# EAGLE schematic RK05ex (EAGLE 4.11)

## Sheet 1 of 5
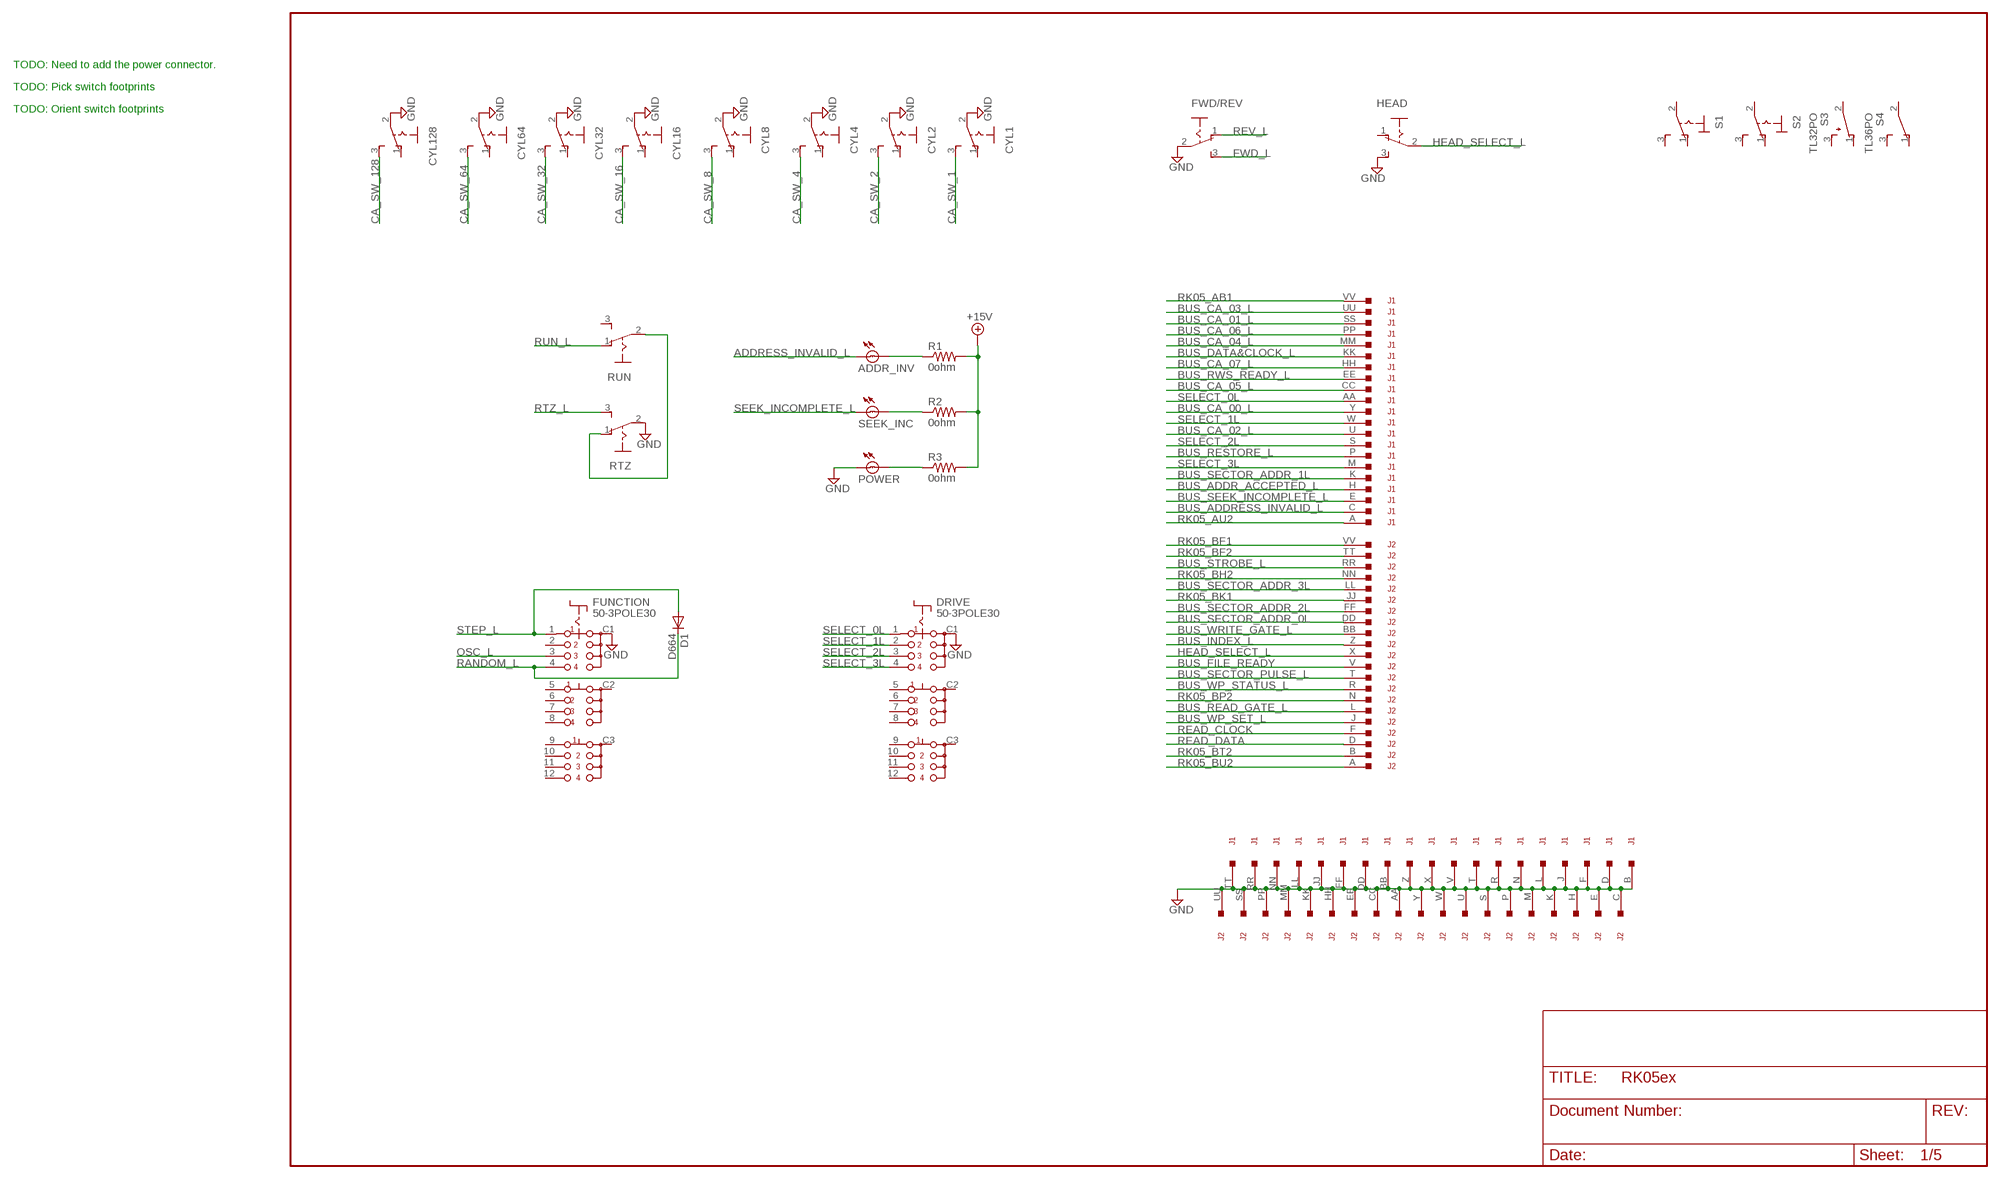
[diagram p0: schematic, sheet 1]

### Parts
ADDR_INV  BULB  [BULB]
CYL1  255SB  [255SB]
CYL2  255SB  [255SB]
CYL4  255SB  [255SB]
CYL8  255SB  [255SB]
CYL16  255SB  [255SB]
CYL32  255SB  [255SB]
CYL64  255SB  [255SB]
CYL128  255SB  [255SB]
D1  D664  1N4148  [DO35-10]
DRIVE  50-3POLE30  [50-3POLE30]
FUNCTION  50-3POLE30  [50-3POLE30]
FWD/REV  255SB  [255SB]
HEAD  255SB  [255SB]
J1  DEC40PINSV  [DEC40PINV]
J2  DEC40PINSV  [DEC40PINV]
POWER  BULB  [BULB]
R1  0ohm  R-US_0207/10  [0207/10]
R2  0ohm  R-US_0207/10  [0207/10]
R3  0ohm  R-US_0207/10  [0207/10]
RTZ  255SB  [255SB]
RUN  255SB  [255SB]
S1  320-916  [320-916]
S2  M9040P  [M9040P]
S3  TL32PO  [TL3XPO]
S4  TL36PO  [TL3XPO]
SEEK_INC  BULB  [BULB]

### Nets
+15V: R1.2 R2.2 R3.2 ; also sheet 3
ADDRESS_INVALID_L: ADDR_INV.B ; also sheet 3
BUS_ADDR_ACCEPTED_L: J1.H ; also sheet 5
BUS_ADDRESS_INVALID_L: J1.C ; also sheet 3,5
BUS_CA_00_L: J1.Y ; also sheet 4,5
BUS_CA_01_L: J1.SS ; also sheet 4,5
BUS_CA_02_L: J1.U ; also sheet 4,5
BUS_CA_03_L: J1.UU ; also sheet 4,5
BUS_CA_04_L: J1.MM ; also sheet 4,5
BUS_CA_05_L: J1.CC ; also sheet 4,5
BUS_CA_06_L: J1.PP ; also sheet 4,5
BUS_CA_07_L: J1.HH ; also sheet 4,5
BUS_DATA&CLOCK_L: J1.KK ; also sheet 2,5
BUS_FILE_READY: J2.V ; also sheet 5
BUS_INDEX_L: J2.Z ; also sheet 2,5
BUS_READ_GATE_L: J2.L ; also sheet 5
BUS_RESTORE_L: J1.P ; also sheet 3,5
BUS_RWS_READY_L: J1.EE ; also sheet 3,5
BUS_SECTOR_ADDR_0L: J2.DD ; also sheet 2,5
BUS_SECTOR_ADDR_1L: J1.K ; also sheet 2,5
BUS_SECTOR_ADDR_2L: J2.FF ; also sheet 2,5
BUS_SECTOR_ADDR_3L: J2.LL ; also sheet 2,5
BUS_SECTOR_PULSE_L: J2.T ; also sheet 5
BUS_SEEK_INCOMPLETE_L: J1.E ; also sheet 3,5
BUS_STROBE_L: J2.RR ; also sheet 3,5
BUS_WP_SET_L: J2.J ; also sheet 5
BUS_WP_STATUS_L: J2.R ; also sheet 5
BUS_WRITE_GATE_L: J2.BB ; also sheet 2,5
CA_SW_1: CYL1.3(S) ; also sheet 4
CA_SW_2: CYL2.3(S) ; also sheet 4
CA_SW_4: CYL4.3(S) ; also sheet 4
CA_SW_8: CYL8.3(S) ; also sheet 4
CA_SW_16: CYL16.3(S) ; also sheet 4
CA_SW_32: CYL32.3(S) ; also sheet 4
CA_SW_64: CYL64.3(S) ; also sheet 4
CA_SW_128: CYL128.3(S) ; also sheet 4
FWD_L: FWD/REV.3(S) ; also sheet 3
GND: CYL1.2(P) CYL2.2(P) CYL4.2(P) CYL8.2(P) CYL16.2(P) CYL32.2(P) CYL64.2(P) CYL128.2(P) DRIVE.C1(A) FUNCTION.C1(A) FWD/REV.2(P) HEAD.3(S) J1.B J1.BB J1.D J1.DD J1.F J1.FF J1.J J1.JJ J1.L J1.LL J1.N J1.NN J1.R J1.RR J1.T J1.TT J1.V J1.X J1.Z J2.AA J2.C J2.CC J2.E J2.EE J2.H J2.HH J2.K J2.KK J2.M J2.MM J2.P J2.PP J2.S J2.SS J2.U J2.UU J2.W J2.Y POWER.B RTZ.2(P) ; also sheet 2,3,4,5
HEAD_SELECT_L: HEAD.2(P) J2.X ; also sheet 5
N$30: RTZ.1(O) RUN.2(P)
N$37: ADDR_INV.A R1.1
N$38: R2.1 SEEK_INC.A
N$39: POWER.A R3.1
OSC_L: FUNCTION.3(A3) ; also sheet 3
RANDOM_L: D1.C FUNCTION.4(A4) ; also sheet 3
READ_CLOCK: J2.F ; also sheet 5
READ_DATA: J2.D ; also sheet 5
REV_L: FWD/REV.1(O) ; also sheet 3
RK05_AB1: J1.VV ; also sheet 5
RK05_AU2: J1.A ; also sheet 5
RK05_BF1: J2.VV ; also sheet 5
RK05_BF2: J2.TT ; also sheet 5
RK05_BH2: J2.NN ; also sheet 5
RK05_BK1: J2.JJ ; also sheet 5
RK05_BP2: J2.N ; also sheet 5
RK05_BT2: J2.B ; also sheet 5
RK05_BU2: J2.A ; also sheet 5
RTZ_L: RTZ.3(S) ; also sheet 3
RUN_L: RUN.1(O) ; also sheet 3
SEEK_INCOMPLETE_L: SEEK_INC.B ; also sheet 3
SELECT_0L: DRIVE.1(A1) J1.AA ; also sheet 5
SELECT_1L: DRIVE.2(A2) J1.W ; also sheet 5
SELECT_2L: DRIVE.3(A3) J1.S ; also sheet 5
SELECT_3L: DRIVE.4(A4) J1.M ; also sheet 5
STEP_L: D1.A FUNCTION.1(A1) ; also sheet 3
Unconnected: CYL1.1(O) CYL2.1(O) CYL4.1(O) CYL8.1(O) CYL16.1(O) CYL32.1(O) CYL64.1(O) CYL128.1(O) DRIVE.5(B1) DRIVE.6(B2) DRIVE.7(B3) DRIVE.8(B4) DRIVE.9(C1) DRIVE.10(C2) DRIVE.11(C3) DRIVE.12(C4) DRIVE.C2(B) DRIVE.C3(C) FUNCTION.2(A2) FUNCTION.5(B1) FUNCTION.6(B2) FUNCTION.7(B3) FUNCTION.8(B4) FUNCTION.9(C1) FUNCTION.10(C2) FUNCTION.11(C3) FUNCTION.12(C4) FUNCTION.C2(B) FUNCTION.C3(C) HEAD.1(O) RUN.3(S) S1.1(O) S1.2(P) S1.3(S) S2.1(O) S2.2(P) S2.3(S) S3.1(O) S3.2(P) S3.3(S) S4.1(O) S4.2(P) S4.3(S)

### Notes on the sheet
- TODO: Need to add the power connector.
- TODO: Pick switch footprints
- TODO: Orient switch footprints

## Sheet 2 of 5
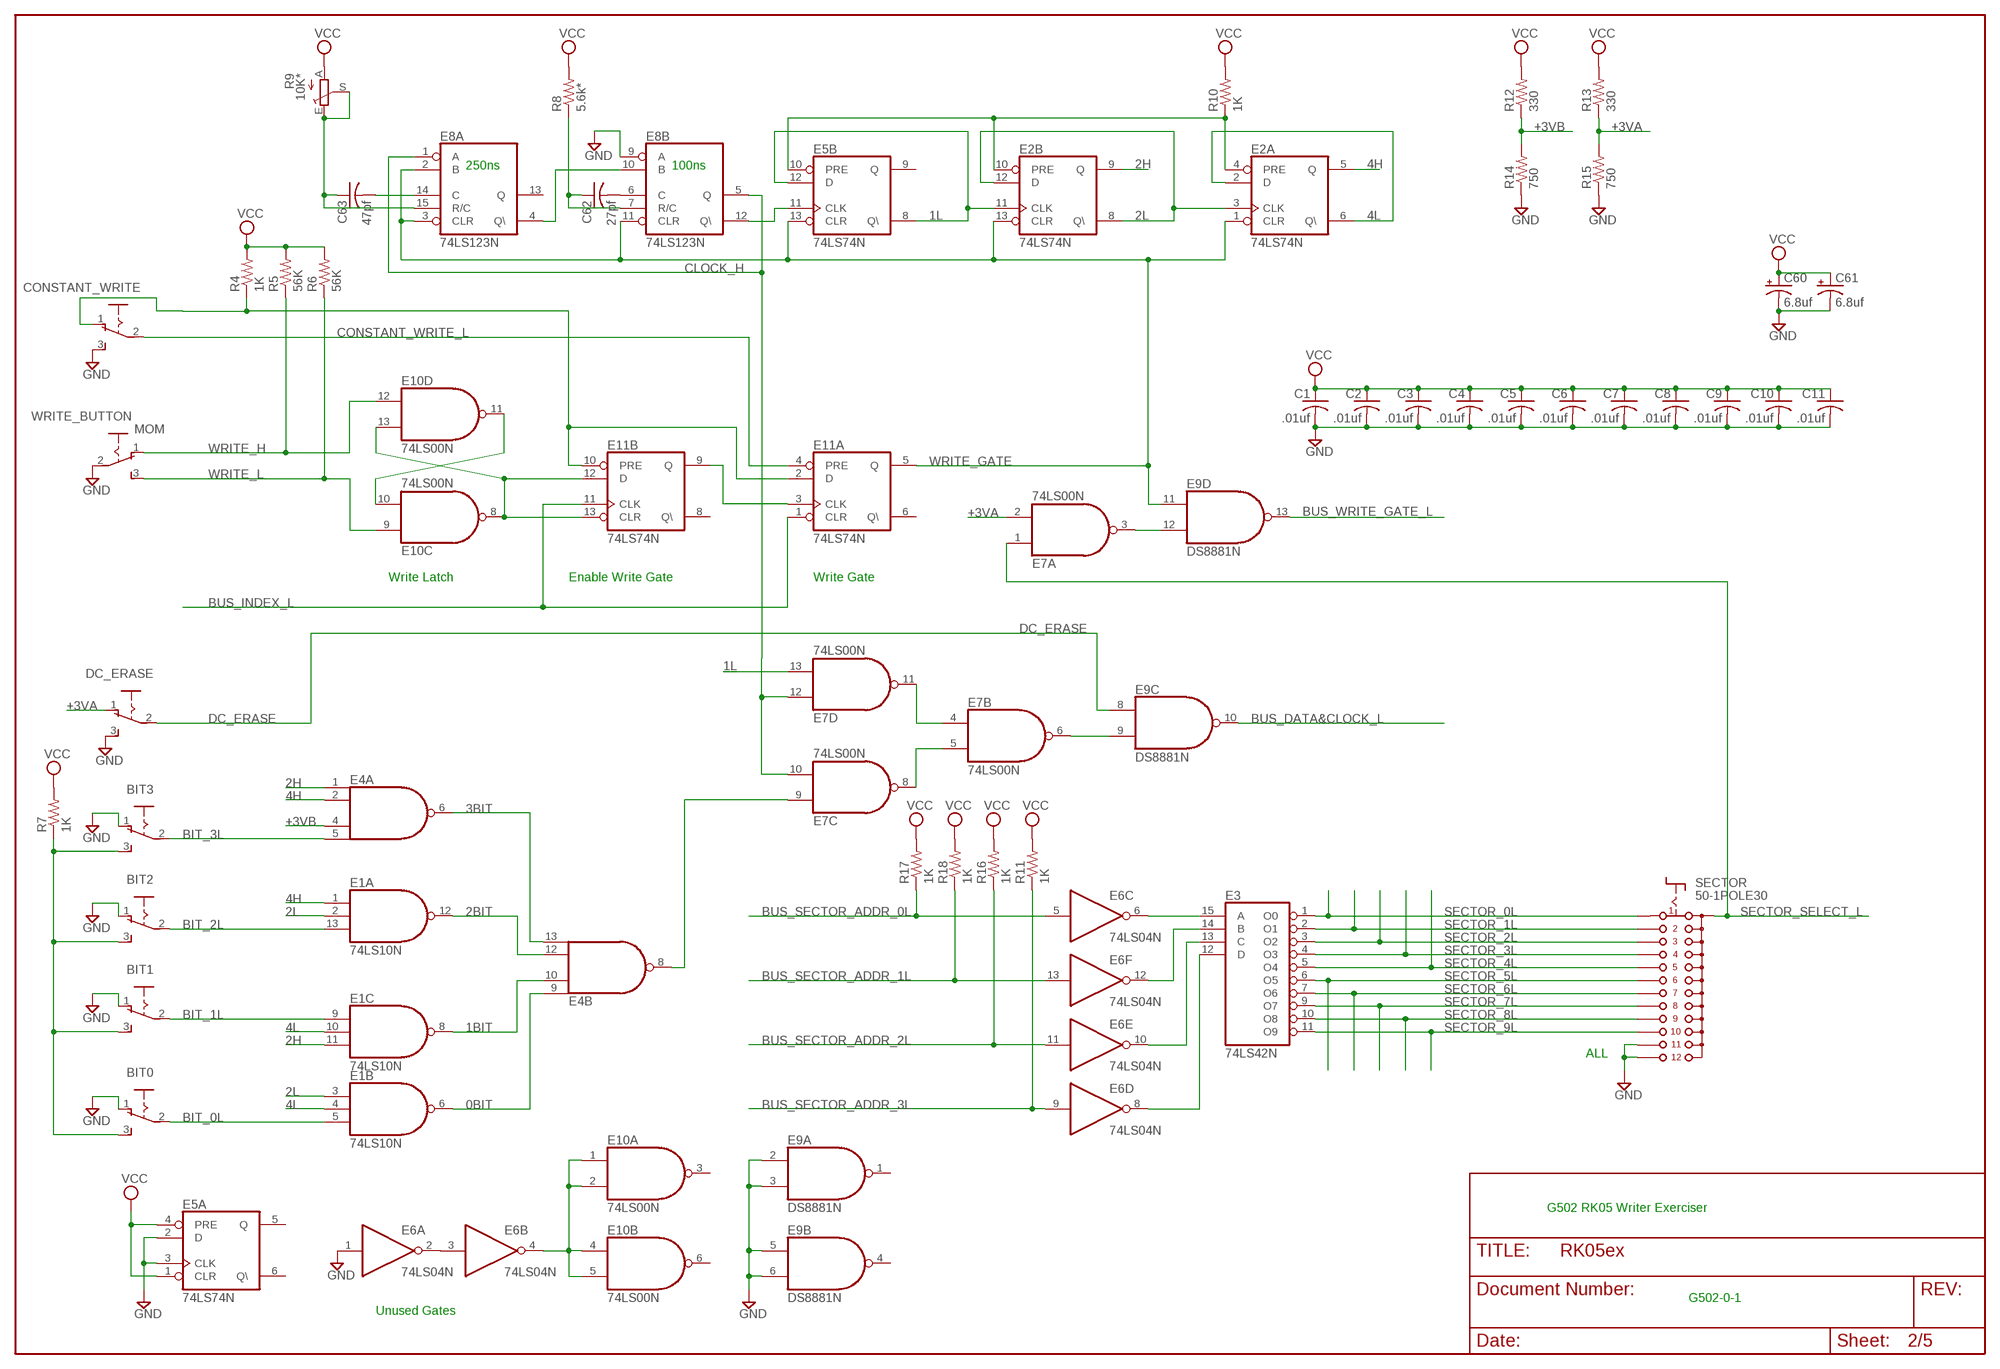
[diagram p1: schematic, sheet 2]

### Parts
BIT0  255SB  [255SB]
BIT1  255SB  [255SB]
BIT2  255SB  [255SB]
BIT3  255SB  [255SB]
C1  .01uf  C-US075-032X103  [C075-032X103]
C2  .01uf  C-US075-032X103  [C075-032X103]
C3  .01uf  C-US075-032X103  [C075-032X103]
C4  .01uf  C-US075-032X103  [C075-032X103]
C5  .01uf  C-US075-032X103  [C075-032X103]
C6  .01uf  C-US075-032X103  [C075-032X103]
C7  .01uf  C-US075-032X103  [C075-032X103]
C8  .01uf  C-US075-032X103  [C075-032X103]
C9  .01uf  C-US075-032X103  [C075-032X103]
C10  .01uf  C-US075-032X103  [C075-032X103]
C11  .01uf  C-US075-032X103  [C075-032X103]
C60  6.8uf  CPOL-USE25-9AXIAL  [E25-9]
C61  6.8uf  CPOL-USE25-9AXIAL  [E25-9]
C62  27pf  C-US075-032X103  [C075-032X103]
C63  47pf  C-US075-032X103  [C075-032X103]
CONSTANT_WRITE  255SB  [255SB]
DC_ERASE  255SB  [255SB]
E1  74LS10N  [DIL14]
E2  74LS74N  [DIL14]
E3  74LS42N  [DIL16]
E4  74LS20N  [DIL14]
E5  74LS74N  [DIL14]
E6  74LS04N  [DIL14]
E7  74LS00N  [DIL14]
E8  74LS123N  [DIL16]
E9  DS8881N  [DIL14]
E10  74LS00N  [DIL14]
E11  74LS74N  [DIL14]
R4  1K  R-US_0207/10  [0207/10]
R5  56K  R-US_0207/10  [0207/10]
R6  56K  R-US_0207/10  [0207/10]
R7  1K  R-US_0207/10  [0207/10]
R8  5.6k*  R-US_0207/10  [0207/10]
R9  10K*  TRIM_EU-B90P  [SP19L]
R10  1K  R-US_0207/10  [0207/10]
R11  1K  R-US_0207/10  [0207/10]
R12  330  R-US_0207/10  [0207/10]
R13  330  R-US_0207/10  [0207/10]
R14  750  R-US_0207/10  [0207/10]
R15  750  R-US_0207/10  [0207/10]
R16  1K  R-US_0207/10  [0207/10]
R17  1K  R-US_0207/10  [0207/10]
R18  1K  R-US_0207/10  [0207/10]
SECTOR  50-1POLE30  [50-1POLE30]
WRITE_BUTTON  MOM  255SB  [255SB]

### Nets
0BIT: E1.6(B:O) E4.9(B:I0)
1.44MHZ: E5.11(B:CLK) E8.12(B:Q\)
1BIT: E1.8(C:O) E4.10(B:I1)
1L: E2.11(B:CLK) E5.8(B:Q\) E5.12(B:D) E7.13(D:I1)
2.88MHZ: E8.4(A:Q\) E8.10(B:B)
2BIT: E1.12(A:O) E4.12(B:I2)
2H: E1.11(C:I2) E2.9(B:Q) E4.1(A:I0)
2L: E1.2(A:I1) E1.3(B:I0) E2.3(A:CLK) E2.8(B:Q\) E2.12(B:D)
3BIT: E4.6(A:O) E4.13(B:I3)
4H: E1.1(A:I0) E2.5(A:Q) E4.2(A:I1)
4L: E1.4(B:I1) E1.10(C:I1) E2.2(A:D) E2.6(A:Q\)
+3VA: DC_ERASE.1(O) E7.2(A:I1) R13.1 R15.2
+3VB: E4.4(A:I2) R12.1 R14.2
+3VC: CONSTANT_WRITE.1(O) E11.2(A:D) E11.10(B:PRE) R4.1
BIT_0L: BIT0.2(P) E1.5(B:I2)
BIT_1L: BIT1.2(P) E1.9(C:I0)
BIT_2L: BIT2.2(P) E1.13(A:I2)
BIT_3L: BIT3.2(P) E4.5(A:I3)
BUS_DATA&CLOCK_L: E9.10(C:O) ; also sheet 1,5
BUS_INDEX_L: E11.1(A:CLR) E11.11(B:CLK) ; also sheet 1,5
BUS_SECTOR_ADDR_0L: E6.5(C:I) R17.1 ; also sheet 1,5
BUS_SECTOR_ADDR_1L: E6.13(F:I) R18.1 ; also sheet 1,5
BUS_SECTOR_ADDR_2L: E6.11(E:I) R16.1 ; also sheet 1,5
BUS_SECTOR_ADDR_3L: E6.9(D:I) R11.1 ; also sheet 1,5
BUS_WRITE_GATE_L: E9.13(D:O) ; also sheet 1,5
CLOCK_H: E7.10(C:I1) E7.12(D:I0) E8.1(A:A) E8.5(B:Q)
CONSTANT_WRITE_L: CONSTANT_WRITE.2(P) E11.4(A:PRE)
DATA_BITS: BIT0.3(S) BIT1.3(S) BIT2.3(S) BIT3.3(S) R7.1
DC_ERASE: DC_ERASE.2(P) E9.8(C:I0)
GND: BIT0.1(O) BIT1.1(O) BIT2.1(O) BIT3.1(O) C1.2 C2.2 C3.2 C4.2 C5.2 C6.2 C7.2 C8.2 C9.2 C10.2 C11.2 C60.- C61.- CONSTANT_WRITE.3(S) DC_ERASE.3(S) E5.2(A:D) E5.3(A:CLK) E6.1(A:I) E8.9(B:A) E9.2(A:I0) E9.3(A:I1) E9.5(B:I0) E9.6(B:I1) R14.1 R15.1 SECTOR.11 SECTOR.12 WRITE_BUTTON.2(P) ; also sheet 1,3,4,5
N$2: E7.6(B:O) E9.9(C:I1)
N$3: E10.8(C:O) E10.13(D:I1) E11.12(B:D) E11.13(B:CLR)
N$4: E10.10(C:I1) E10.11(D:O)
N$5: E2.4(A:PRE) E2.10(B:PRE) E5.10(B:PRE) R10.1
N$6: E7.4(B:I0) E7.11(D:O)
N$7: E7.5(B:I1) E7.8(C:O)
N$8: E11.3(A:CLK) E11.9(B:Q)
N$9: E4.8(B:O) E7.9(C:I0)
N$11: C63.2 E8.14(A:C)
N$12: C62.2 E8.6(B:C)
N$13: C63.1 E8.15(A:R/C) R9.E R9.S
N$14: C62.1 E8.7(B:R/C) R8.1
N$15: E7.3(A:O) E9.12(D:I1)
N$29: E3.15(A) E6.6(C:O)
N$31: E3.14(B) E6.12(F:O)
N$32: E3.13(C) E6.10(E:O)
N$33: E3.12(D) E6.8(D:O)
N$34: E6.2(A:O) E6.3(B:I)
N$36: E6.4(B:O) E10.1(A:I0) E10.2(A:I1) E10.4(B:I0) E10.5(B:I1)
SECTOR_0L: E3.1(O0) SECTOR.1
SECTOR_1L: E3.2(O1) SECTOR.2
SECTOR_2L: E3.3(O2) SECTOR.3
SECTOR_3L: E3.4(O3) SECTOR.4
SECTOR_4L: E3.5(O4) SECTOR.5
SECTOR_5L: E3.6(O5) SECTOR.6
SECTOR_6L: E3.7(O6) SECTOR.7
SECTOR_7L: E3.9(O7) SECTOR.8
SECTOR_8L: E3.10(O8) SECTOR.9
SECTOR_9L: E3.11(O9) SECTOR.10
SECTOR_SELECT_L: E7.1(A:I0) SECTOR.C(A)
VCC: C1.1 C2.1 C3.1 C4.1 C5.1 C6.1 C7.1 C8.1 C9.1 C10.1 C11.1 C60.+ C61.+ E5.1(A:CLR) E5.4(A:PRE) R4.2 R5.2 R6.2 R7.2 R8.2 R9.A R10.2 R11.2 R12.2 R13.2 R16.2 R17.2 R18.2 ; also sheet 3,4,5
WRITE_GATE: E2.1(A:CLR) E2.13(B:CLR) E5.13(B:CLR) E8.2(A:B) E8.3(A:CLR) E8.11(B:CLR) E9.11(D:I0) E11.5(A:Q)
WRITE_H: E10.12(D:I0) R5.1 WRITE_BUTTON.1(O)
WRITE_L: E10.9(C:I0) R6.1 WRITE_BUTTON.3(S)
Unconnected: E5.5(A:Q) E5.6(A:Q\) E5.9(B:Q) E8.13(A:Q) E9.1(A:O) E9.4(B:O) E10.3(A:O) E10.6(B:O) E11.6(A:Q\) E11.8(B:Q\)

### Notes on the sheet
- 250ns | 100ns
- Write Latch | Enable Write Gate | Write Gate
- ALL
- G502 RK05 Writer Exerciser
- G502-0-1
- Unused Gates

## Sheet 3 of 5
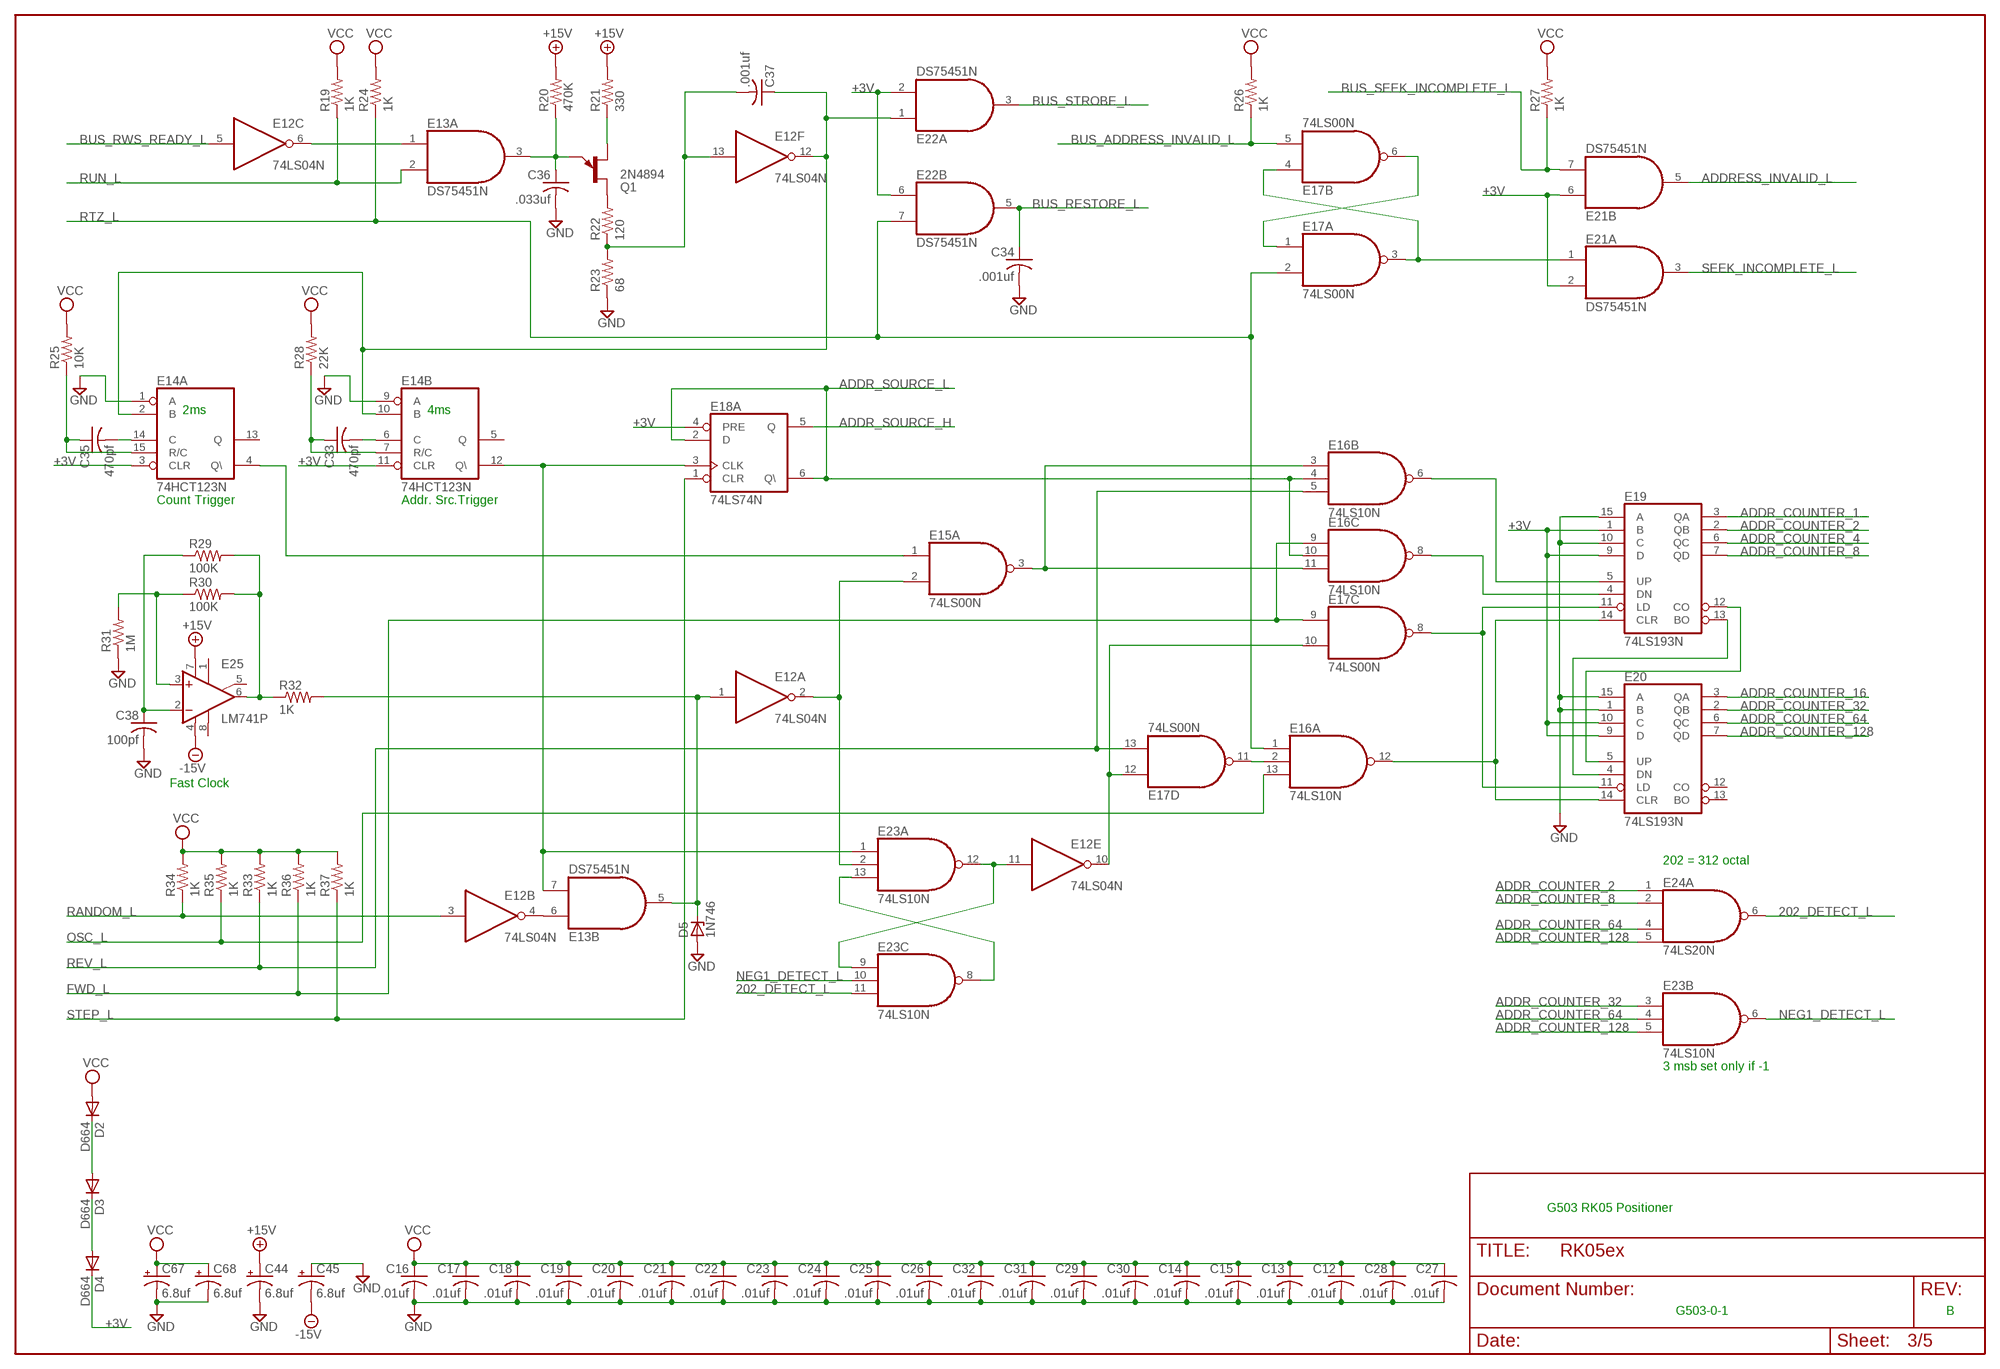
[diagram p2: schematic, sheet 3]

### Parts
C12  .01uf  C-US075-032X103  [C075-032X103]
C13  .01uf  C-US075-032X103  [C075-032X103]
C14  .01uf  C-US075-032X103  [C075-032X103]
C15  .01uf  C-US075-032X103  [C075-032X103]
C16  .01uf  C-US075-032X103  [C075-032X103]
C17  .01uf  C-US075-032X103  [C075-032X103]
C18  .01uf  C-US075-032X103  [C075-032X103]
C19  .01uf  C-US075-032X103  [C075-032X103]
C20  .01uf  C-US075-032X103  [C075-032X103]
C21  .01uf  C-US075-032X103  [C075-032X103]
C22  .01uf  C-US075-032X103  [C075-032X103]
C23  .01uf  C-US075-032X103  [C075-032X103]
C24  .01uf  C-US075-032X103  [C075-032X103]
C25  .01uf  C-US075-032X103  [C075-032X103]
C26  .01uf  C-US075-032X103  [C075-032X103]
C27  .01uf  C-US075-032X103  [C075-032X103]
C28  .01uf  C-US075-032X103  [C075-032X103]
C29  .01uf  C-US075-032X103  [C075-032X103]
C30  .01uf  C-US075-032X103  [C075-032X103]
C31  .01uf  C-US075-032X103  [C075-032X103]
C32  .01uf  C-US075-032X103  [C075-032X103]
C33  470pf  C-US075-032X103  [C075-032X103]
C34  .001uf  C-US075-032X103  [C075-032X103]
C35  470pf  C-US075-032X103  [C075-032X103]
C36  .033uf  C-US075-032X103  [C075-032X103]
C37  .001uf  C-US075-032X103  [C075-032X103]
C38  100pf  C-US075-032X103  [C075-032X103]
C44  6.8uf  CPOL-USE25-9AXIAL  [E25-9]
C45  6.8uf  CPOL-USE25-9AXIAL  [E25-9]
C67  6.8uf  CPOL-USE25-9AXIAL  [E25-9]
C68  6.8uf  CPOL-USE25-9AXIAL  [E25-9]
D2  D664  1N4148  [DO35-10]
D3  D664  1N4148  [DO35-10]
D4  D664  1N4148  [DO35-10]
D5  1N746  ZENER-DIODEDO35Z10  [DO35Z10]
E12  74LS04N  [DIL14]
E13  DS75451N  [DIL08]
E14  74HCT123N  [DIL16]
E15  74LS00N  [DIL14]
E16  74LS10N  74AS10N  [DIL14]
E17  74LS00N  [DIL14]
E18  74LS74N  [DIL14]
E19  74LS193N  [DIL16]
E20  74LS193N  [DIL16]
E21  DS75451N  [DIL08]
E22  DS75451N  [DIL08]
E23  74LS10N  74AS10N  [DIL14]
E24  74LS20N  [DIL14]
E25  LM741P  [DIL08]
Q1  2N4894  2N4870  [TO92E]
R19  1K  R-US_0207/10  [0207/10]
R20  470K  R-US_0207/10  [0207/10]
R21  330  R-US_0207/10  [0207/10]
R22  120  R-US_0207/10  [0207/10]
R23  68  R-US_0207/10  [0207/10]
R24  1K  R-US_0207/10  [0207/10]
R25  10K  R-US_0207/10  [0207/10]
R26  1K  R-US_0207/10  [0207/10]
R27  1K  R-US_0207/10  [0207/10]
R28  22K  R-US_0207/10  [0207/10]
R29  100K  R-US_0207/10  [0207/10]
R30  100K  R-US_0207/10  [0207/10]
R31  1M  R-US_0207/10  [0207/10]
R32  1K  R-US_0207/10  [0207/10]
R33  1K  R-US_0207/10  [0207/10]
R34  1K  R-US_0207/10  [0207/10]
R35  1K  R-US_0207/10  [0207/10]
R36  1K  R-US_0207/10  [0207/10]
R37  1K  R-US_0207/10  [0207/10]

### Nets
202_DETECT_L: E23.11(C:I2) E24.6(A:O)
+3V: D4.C E14.3(A:CLR) E14.11(B:CLR) E18.4(A:PRE) E19.1(B) E19.9(D) E20.9(D) E20.10(C) E21.2(A:I1) E21.6(B:I0) E22.2(A:I1) E22.6(B:I0)
+15V: C44.+ E25.7(V+) R20.2 R21.2 ; also sheet 1
-15V: C45.- E25.4(V-)
ADDR_COUNTER_1: E19.3(QA) ; also sheet 4
ADDR_COUNTER_2: E19.2(QB) E24.1(A:I0) ; also sheet 4
ADDR_COUNTER_4: E19.6(QC) ; also sheet 4
ADDR_COUNTER_8: E19.7(QD) E24.2(A:I1) ; also sheet 4
ADDR_COUNTER_16: E20.3(QA) ; also sheet 4
ADDR_COUNTER_32: E20.2(QB) E23.3(B:I0) ; also sheet 4
ADDR_COUNTER_64: E20.6(QC) E23.4(B:I1) E24.4(A:I2) ; also sheet 4
ADDR_COUNTER_128: E20.7(QD) E23.5(B:I2) E24.5(A:I3) ; also sheet 4
ADDR_SOURCE_H: E18.5(A:Q) ; also sheet 4
ADDR_SOURCE_L: E16.4(B:I1) E16.10(C:I1) E18.2(A:D) E18.6(A:Q\) ; also sheet 4
ADDRESS_INVALID_L: E21.5(B:O) ; also sheet 1
BUS_ADDRESS_INVALID_L: E17.5(B:I1) R26.1 ; also sheet 1,5
BUS_RESTORE_L: C34.1 E22.5(B:O) ; also sheet 1,5
BUS_RWS_READY_L: E12.5(C:I) ; also sheet 1,5
BUS_SEEK_INCOMPLETE_L: E21.7(B:I1) R27.1 ; also sheet 1,5
BUS_STROBE_L: E22.3(A:O) ; also sheet 1,5
FWD_L: E16.9(C:I0) E17.9(C:I0) R36.1 ; also sheet 1
GND: C12.2 C13.2 C14.2 C15.2 C16.2 C17.2 C18.2 C19.2 C20.2 C21.2 C22.2 C23.2 C24.2 C25.2 C26.2 C27.2 C28.2 C29.2 C30.2 C31.2 C32.2 C34.2 C36.2 C38.2 C44.- C45.+ C67.- C68.- D5.A E14.1(A:A) E14.9(B:A) E19.10(C) E19.15(A) E20.1(B) E20.15(A) R23.1 R31.1 ; also sheet 1,2,4,5
N$1: E12.6(C:O) E13.1(A:I0)
N$10: C36.1 E13.3(A:O) Q1.E R20.1
N$16: Q1.B1 R21.1
N$17: Q1.B2 R22.2
N$18: C37.2 E12.13(F:I) R22.1 R23.2
N$19: C37.1 E12.12(F:O) E14.2(A:B) E14.10(B:B) E22.1(A:I0)
N$20: E17.1(A:I0) E17.6(B:O)
N$21: E17.3(A:O) E17.4(B:I0) E21.1(A:I0)
N$22: C35.1 E14.15(A:R/C) R25.1
N$23: C35.2 E14.14(A:C)
N$24: C33.1 E14.7(B:R/C) R28.1
N$25: C33.2 E14.6(B:C)
N$26: E19.13(BO) E20.4(DN)
N$27: E19.12(CO) E20.5(UP)
N$28: E16.6(B:O) E19.5(UP)
N$35: E16.8(C:O) E19.4(DN)
N$40: E17.8(C:O) E19.11(LD) E20.11(LD)
N$41: E16.12(A:O) E19.14(CLR) E20.14(CLR)
N$42: C38.1 E25.2(-IN) R29.1
N$43: E25.6(OUT) R29.2 R30.2 R32.1
N$44: E25.3(+IN) R30.1 R31.2
N$46: E12.2(A:O) E15.2(A:I1) E23.2(A:I1)
N$47: E14.4(A:Q\) E15.1(A:I0)
N$48: D2.C D3.A
N$53: D3.C D4.A
N$55: E12.4(B:O) E13.6(B:I0)
N$57: E13.7(B:I1) E14.12(B:Q\) E18.3(A:CLK) E23.1(A:I0)
N$58: D5.C E12.1(A:I) E13.5(B:O) R32.2
N$59: E15.3(A:O) E16.3(B:I0) E16.11(C:I2)
N$60: E23.8(C:O) E23.13(A:I2)
N$61: E12.11(E:I) E23.9(C:I0) E23.12(A:O)
N$62: E16.2(A:I1) E17.11(D:O)
N$63: E12.10(E:O) E17.10(C:I1) E17.12(D:I0)
NEG1_DETECT_L: E23.6(B:O) E23.10(C:I1)
OSC_L: E16.13(A:I2) R35.1 ; also sheet 1
RANDOM_L: E12.3(B:I) R34.1 ; also sheet 1
REV_L: E16.5(B:I2) E17.13(D:I1) R33.1 ; also sheet 1
RTZ_L: E16.1(A:I0) E17.2(A:I1) E22.7(B:I1) R24.1 ; also sheet 1
RUN_L: E13.2(A:I1) R19.1 ; also sheet 1
SEEK_INCOMPLETE_L: E21.3(A:O) ; also sheet 1
STEP_L: E18.1(A:CLR) R37.1 ; also sheet 1
VCC: C12.1 C13.1 C14.1 C15.1 C16.1 C17.1 C18.1 C19.1 C20.1 C21.1 C22.1 C23.1 C24.1 C25.1 C26.1 C27.1 C28.1 C29.1 C30.1 C31.1 C32.1 C67.+ C68.+ D2.A R19.2 R24.2 R25.2 R26.2 R27.2 R28.2 R33.2 R34.2 R35.2 R36.2 R37.2 ; also sheet 2,4,5
Unconnected: E14.5(B:Q) E14.13(A:Q) E20.12(CO) E20.13(BO) E25.1(ON1) E25.5(ON2) E25.8(OPT)

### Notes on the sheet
- 2ms | 4ms
- Count Trigger | Addr. Src.Trigger
- Fast Clock
- 202 = 312 octal
- 3 msb set only if -1
- G503 RK05 Positioner
- G503-0-1 | B

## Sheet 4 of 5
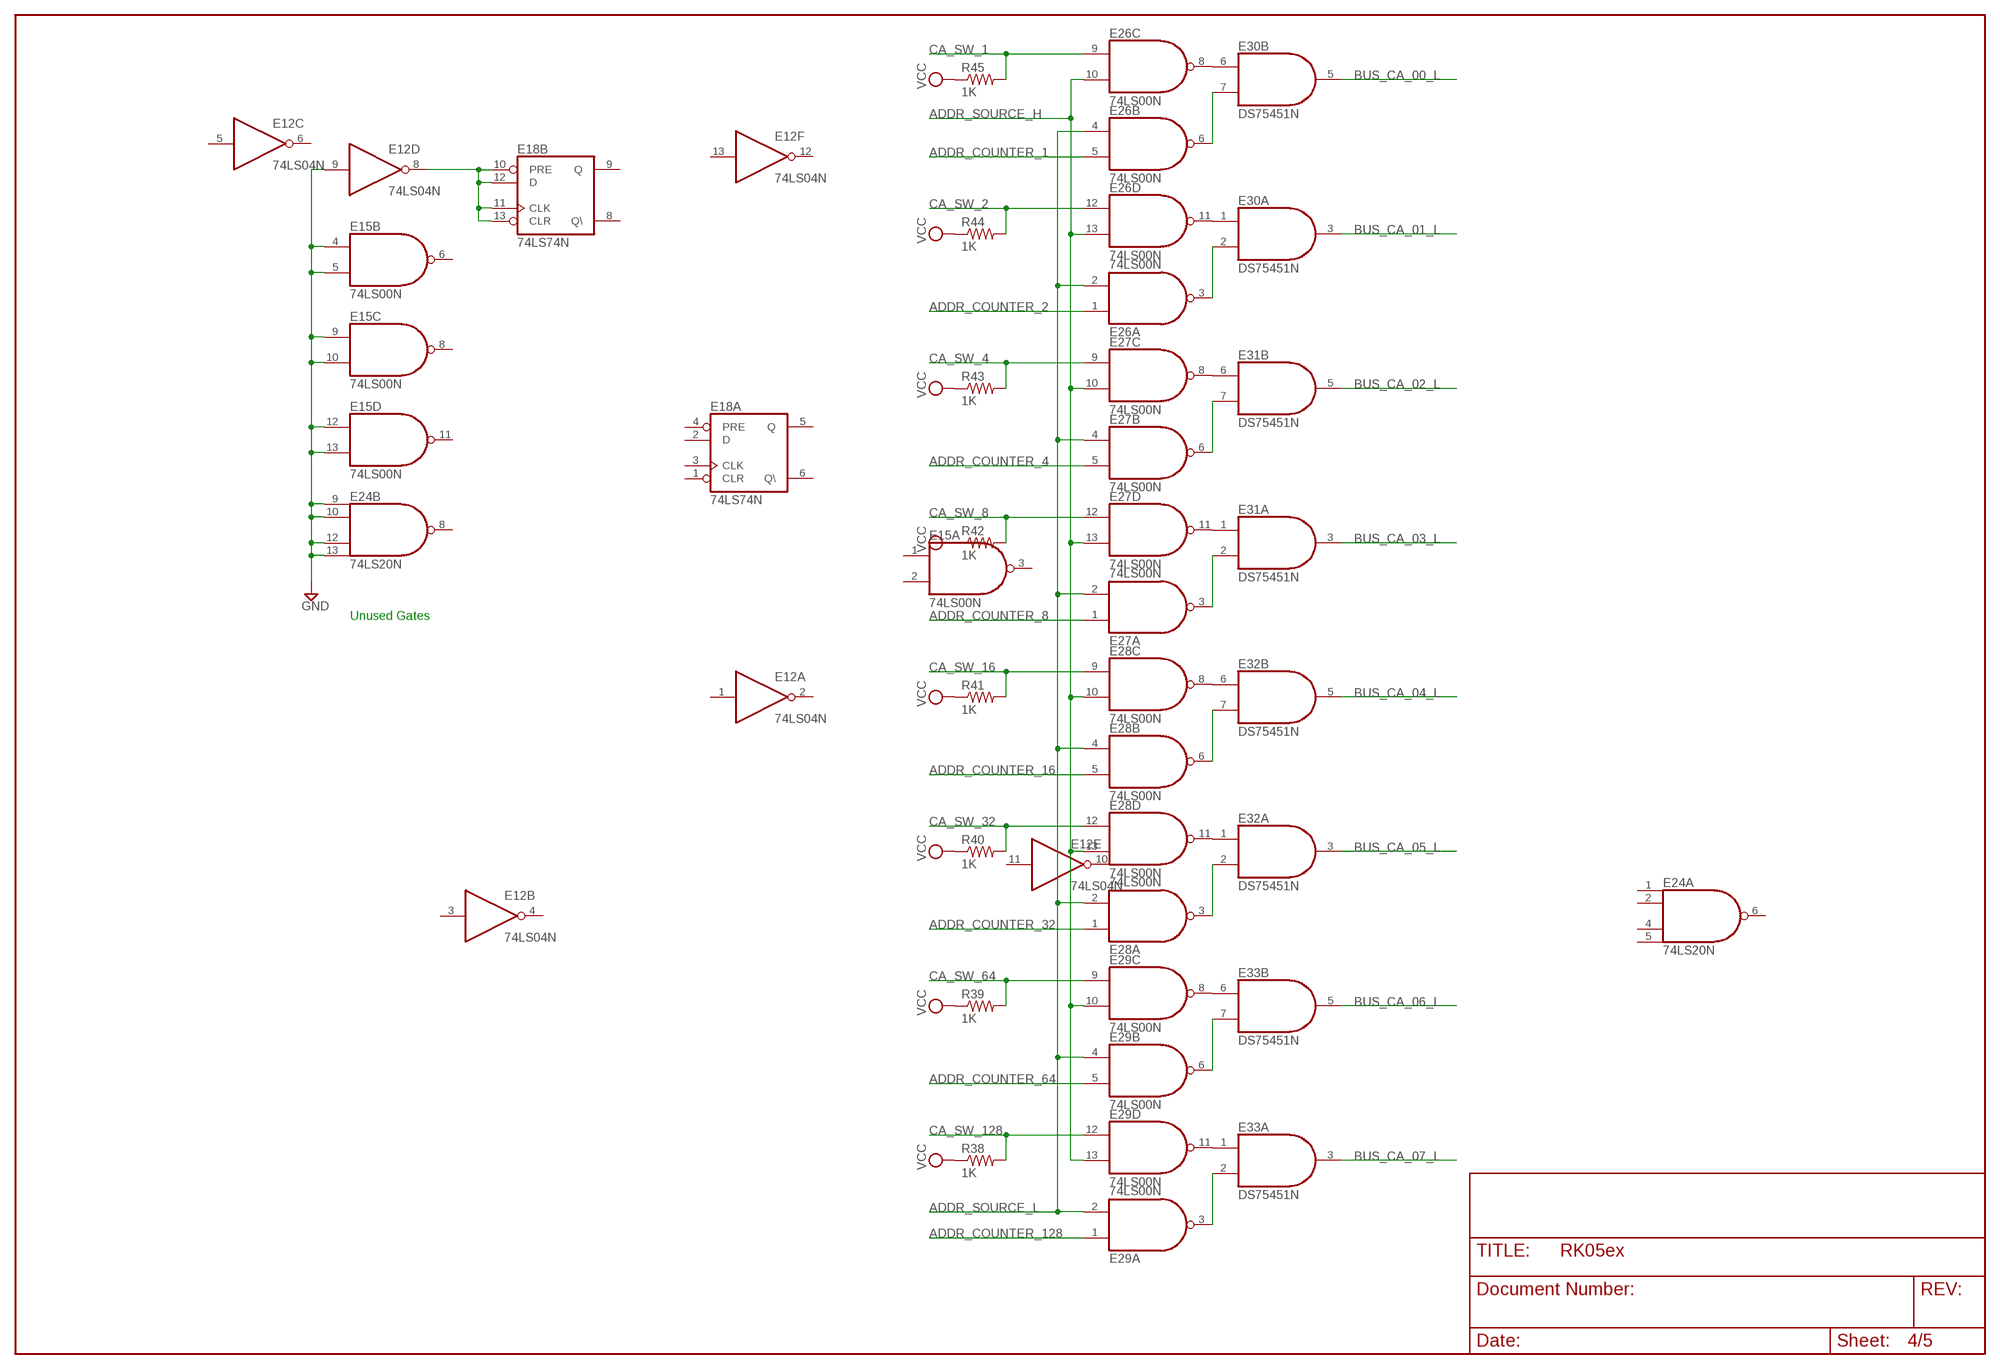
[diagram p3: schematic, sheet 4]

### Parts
E26  74LS00N  [DIL14]
E27  74LS00N  [DIL14]
E28  74LS00N  [DIL14]
E29  74LS00N  [DIL14]
E30  DS75451N  [DIL08]
E31  DS75451N  [DIL08]
E32  DS75451N  [DIL08]
E33  DS75451N  [DIL08]
R38  1K  R-US_0207/10  [0207/10]
R39  1K  R-US_0207/10  [0207/10]
R40  1K  R-US_0207/10  [0207/10]
R41  1K  R-US_0207/10  [0207/10]
R42  1K  R-US_0207/10  [0207/10]
R43  1K  R-US_0207/10  [0207/10]
R44  1K  R-US_0207/10  [0207/10]
R45  1K  R-US_0207/10  [0207/10]

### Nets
ADDR_COUNTER_1: E26.5(B:I1) ; also sheet 3
ADDR_COUNTER_2: E26.1(A:I0) ; also sheet 3
ADDR_COUNTER_4: E27.5(B:I1) ; also sheet 3
ADDR_COUNTER_8: E27.1(A:I0) ; also sheet 3
ADDR_COUNTER_16: E28.5(B:I1) ; also sheet 3
ADDR_COUNTER_32: E28.1(A:I0) ; also sheet 3
ADDR_COUNTER_64: E29.5(B:I1) ; also sheet 3
ADDR_COUNTER_128: E29.1(A:I0) ; also sheet 3
ADDR_SOURCE_H: E26.10(C:I1) E26.13(D:I1) E27.10(C:I1) E27.13(D:I1) E28.10(C:I1) E28.13(D:I1) E29.10(C:I1) E29.13(D:I1) ; also sheet 3
ADDR_SOURCE_L: E26.2(A:I1) E26.4(B:I0) E27.2(A:I1) E27.4(B:I0) E28.2(A:I1) E28.4(B:I0) E29.2(A:I1) E29.4(B:I0) ; also sheet 3
BUS_CA_00_L: E30.5(B:O) ; also sheet 1,5
BUS_CA_01_L: E30.3(A:O) ; also sheet 1,5
BUS_CA_02_L: E31.5(B:O) ; also sheet 1,5
BUS_CA_03_L: E31.3(A:O) ; also sheet 1,5
BUS_CA_04_L: E32.5(B:O) ; also sheet 1,5
BUS_CA_05_L: E32.3(A:O) ; also sheet 1,5
BUS_CA_06_L: E33.5(B:O) ; also sheet 1,5
BUS_CA_07_L: E33.3(A:O) ; also sheet 1,5
CA_SW_1: E26.9(C:I0) R45.2 ; also sheet 1
CA_SW_2: E26.12(D:I0) R44.2 ; also sheet 1
CA_SW_4: E27.9(C:I0) R43.2 ; also sheet 1
CA_SW_8: E27.12(D:I0) R42.2 ; also sheet 1
CA_SW_16: E28.9(C:I0) R41.2 ; also sheet 1
CA_SW_32: E28.12(D:I0) R40.2 ; also sheet 1
CA_SW_64: E29.9(C:I0) R39.2 ; also sheet 1
CA_SW_128: E29.12(D:I0) R38.2 ; also sheet 1
GND: E12.9(D:I) E15.4(B:I0) E15.5(B:I1) E15.9(C:I0) E15.10(C:I1) E15.12(D:I0) E15.13(D:I1) E24.9(B:I0) E24.10(B:I1) E24.12(B:I2) E24.13(B:I3) ; also sheet 1,2,3,5
N$64: E26.6(B:O) E30.7(B:I1)
N$65: E26.8(C:O) E30.6(B:I0)
N$66: E26.3(A:O) E30.2(A:I1)
N$67: E26.11(D:O) E30.1(A:I0)
N$68: E27.8(C:O) E31.6(B:I0)
N$69: E27.6(B:O) E31.7(B:I1)
N$70: E27.11(D:O) E31.1(A:I0)
N$71: E27.3(A:O) E31.2(A:I1)
N$72: E28.6(B:O) E32.7(B:I1)
N$73: E28.3(A:O) E32.2(A:I1)
N$75: E29.6(B:O) E33.7(B:I1)
N$76: E29.3(A:O) E33.2(A:I1)
N$77: E29.11(D:O) E33.1(A:I0)
N$78: E29.8(C:O) E33.6(B:I0)
N$80: E28.11(D:O) E32.1(A:I0)
N$81: E28.8(C:O) E32.6(B:I0)
N$82: E12.8(D:O) E18.10(B:PRE) E18.11(B:CLK) E18.12(B:D) E18.13(B:CLR)
VCC: R38.1 R39.1 R40.1 R41.1 R42.1 R43.1 R44.1 R45.1 ; also sheet 2,3,5
Unconnected: E15.6(B:O) E15.8(C:O) E15.11(D:O) E18.8(B:Q\) E18.9(B:Q) E24.8(B:O)

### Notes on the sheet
- Unused Gates

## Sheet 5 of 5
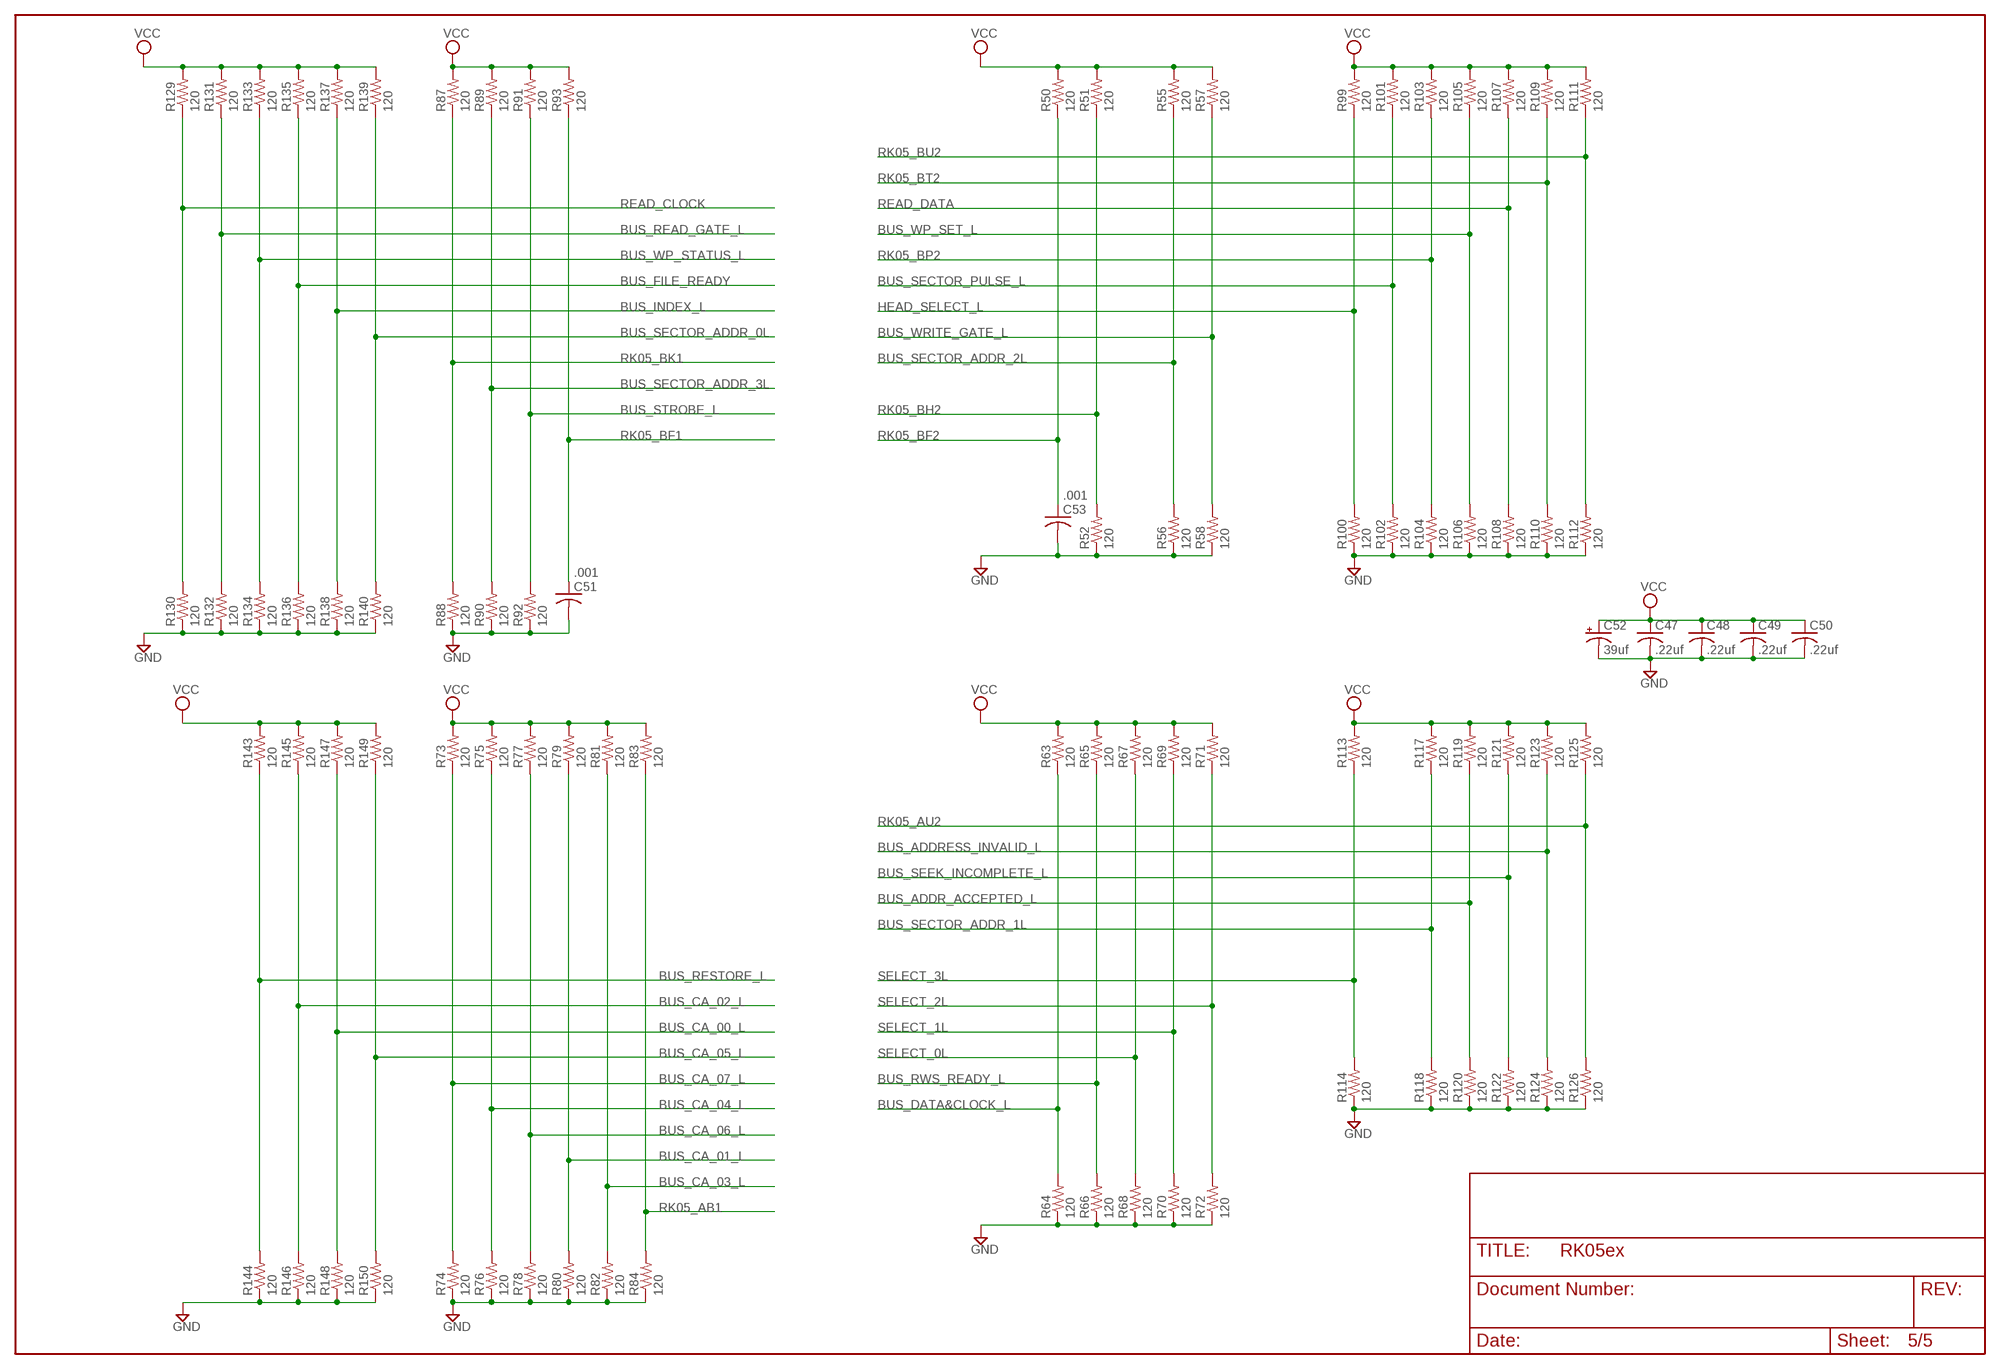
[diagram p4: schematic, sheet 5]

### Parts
C47  .22uf  C-US050-025X075  [C050-025X075]
C48  .22uf  C-US050-025X075  [C050-025X075]
C49  .22uf  C-US050-025X075  [C050-025X075]
C50  .22uf  C-US050-025X075  [C050-025X075]
C51  .001  C-US050-025X075  [C050-025X075]
C52  39uf  CPOL-USE15-5AXIAL  [E15-5]
C53  .001  C-US050-025X075  [C050-025X075]
R50  120  R-US_0207/10  [0207/10]
R51  120  R-US_0207/10  [0207/10]
R52  120  R-US_0207/10  [0207/10]
R55  120  R-US_0207/10  [0207/10]
R56  120  R-US_0207/10  [0207/10]
R57  120  R-US_0207/10  [0207/10]
R58  120  R-US_0207/10  [0207/10]
R63  120  R-US_0207/10  [0207/10]
R64  120  R-US_0207/10  [0207/10]
R65  120  R-US_0207/10  [0207/10]
R66  120  R-US_0207/10  [0207/10]
R67  120  R-US_0207/10  [0207/10]
R68  120  R-US_0207/10  [0207/10]
R69  120  R-US_0207/10  [0207/10]
R70  120  R-US_0207/10  [0207/10]
R71  120  R-US_0207/10  [0207/10]
R72  120  R-US_0207/10  [0207/10]
R73  120  R-US_0207/10  [0207/10]
R74  120  R-US_0207/10  [0207/10]
R75  120  R-US_0207/10  [0207/10]
R76  120  R-US_0207/10  [0207/10]
R77  120  R-US_0207/10  [0207/10]
R78  120  R-US_0207/10  [0207/10]
R79  120  R-US_0207/10  [0207/10]
R80  120  R-US_0207/10  [0207/10]
R81  120  R-US_0207/10  [0207/10]
R82  120  R-US_0207/10  [0207/10]
R83  120  R-US_0207/10  [0207/10]
R84  120  R-US_0207/10  [0207/10]
R87  120  R-US_0207/10  [0207/10]
R88  120  R-US_0207/10  [0207/10]
R89  120  R-US_0207/10  [0207/10]
R90  120  R-US_0207/10  [0207/10]
R91  120  R-US_0207/10  [0207/10]
R92  120  R-US_0207/10  [0207/10]
R93  120  R-US_0207/10  [0207/10]
R99  120  R-US_0207/10  [0207/10]
R100  120  R-US_0207/10  [0207/10]
R101  120  R-US_0207/10  [0207/10]
R102  120  R-US_0207/10  [0207/10]
R103  120  R-US_0207/10  [0207/10]
R104  120  R-US_0207/10  [0207/10]
R105  120  R-US_0207/10  [0207/10]
R106  120  R-US_0207/10  [0207/10]
R107  120  R-US_0207/10  [0207/10]
R108  120  R-US_0207/10  [0207/10]
R109  120  R-US_0207/10  [0207/10]
R110  120  R-US_0207/10  [0207/10]
R111  120  R-US_0207/10  [0207/10]
R112  120  R-US_0207/10  [0207/10]
R113  120  R-US_0207/10  [0207/10]
R114  120  R-US_0207/10  [0207/10]
R117  120  R-US_0207/10  [0207/10]
R118  120  R-US_0207/10  [0207/10]
R119  120  R-US_0207/10  [0207/10]
R120  120  R-US_0207/10  [0207/10]
R121  120  R-US_0207/10  [0207/10]
R122  120  R-US_0207/10  [0207/10]
R123  120  R-US_0207/10  [0207/10]
R124  120  R-US_0207/10  [0207/10]
R125  120  R-US_0207/10  [0207/10]
R126  120  R-US_0207/10  [0207/10]
R129  120  R-US_0207/10  [0207/10]
R130  120  R-US_0207/10  [0207/10]
R131  120  R-US_0207/10  [0207/10]
R132  120  R-US_0207/10  [0207/10]
R133  120  R-US_0207/10  [0207/10]
R134  120  R-US_0207/10  [0207/10]
R135  120  R-US_0207/10  [0207/10]
R136  120  R-US_0207/10  [0207/10]
R137  120  R-US_0207/10  [0207/10]
R138  120  R-US_0207/10  [0207/10]
R139  120  R-US_0207/10  [0207/10]
R140  120  R-US_0207/10  [0207/10]
R143  120  R-US_0207/10  [0207/10]
R144  120  R-US_0207/10  [0207/10]
R145  120  R-US_0207/10  [0207/10]
R146  120  R-US_0207/10  [0207/10]
R147  120  R-US_0207/10  [0207/10]
R148  120  R-US_0207/10  [0207/10]
R149  120  R-US_0207/10  [0207/10]
R150  120  R-US_0207/10  [0207/10]

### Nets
BUS_ADDR_ACCEPTED_L: R119.1 R120.2 ; also sheet 1
BUS_ADDRESS_INVALID_L: R123.1 R124.2 ; also sheet 1,3
BUS_CA_00_L: R147.1 R148.2 ; also sheet 1,4
BUS_CA_01_L: R79.1 R80.2 ; also sheet 1,4
BUS_CA_02_L: R145.1 R146.2 ; also sheet 1,4
BUS_CA_03_L: R81.1 R82.2 ; also sheet 1,4
BUS_CA_04_L: R75.1 R76.2 ; also sheet 1,4
BUS_CA_05_L: R149.1 R150.2 ; also sheet 1,4
BUS_CA_06_L: R77.1 R78.2 ; also sheet 1,4
BUS_CA_07_L: R73.1 R74.2 ; also sheet 1,4
BUS_DATA&CLOCK_L: R63.1 R64.2 ; also sheet 1,2
BUS_FILE_READY: R135.1 R136.2 ; also sheet 1
BUS_INDEX_L: R137.1 R138.2 ; also sheet 1,2
BUS_READ_GATE_L: R131.1 R132.2 ; also sheet 1
BUS_RESTORE_L: R143.1 R144.2 ; also sheet 1,3
BUS_RWS_READY_L: R65.1 R66.2 ; also sheet 1,3
BUS_SECTOR_ADDR_0L: R139.1 R140.2 ; also sheet 1,2
BUS_SECTOR_ADDR_1L: R117.1 R118.2 ; also sheet 1,2
BUS_SECTOR_ADDR_2L: R55.1 R56.2 ; also sheet 1,2
BUS_SECTOR_ADDR_3L: R89.1 R90.2 ; also sheet 1,2
BUS_SECTOR_PULSE_L: R101.1 R102.2 ; also sheet 1
BUS_SEEK_INCOMPLETE_L: R121.1 R122.2 ; also sheet 1,3
BUS_STROBE_L: R91.1 R92.2 ; also sheet 1,3
BUS_WP_SET_L: R105.1 R106.2 ; also sheet 1
BUS_WP_STATUS_L: R133.1 R134.2 ; also sheet 1
BUS_WRITE_GATE_L: R57.1 R58.2 ; also sheet 1,2
GND: C47.2 C48.2 C49.2 C50.2 C51.2 C52.- C53.2 R52.1 R56.1 R58.1 R64.1 R66.1 R68.1 R70.1 R72.1 R74.1 R76.1 R78.1 R80.1 R82.1 R84.1 R88.1 R90.1 R92.1 R100.1 R102.1 R104.1 R106.1 R108.1 R110.1 R112.1 R114.1 R118.1 R120.1 R122.1 R124.1 R126.1 R130.1 R132.1 R134.1 R136.1 R138.1 R140.1 R144.1 R146.1 R148.1 R150.1 ; also sheet 1,2,3,4
HEAD_SELECT_L: R99.1 R100.2 ; also sheet 1
READ_CLOCK: R129.1 R130.2 ; also sheet 1
READ_DATA: R107.1 R108.2 ; also sheet 1
RK05_AB1: R83.1 R84.2 ; also sheet 1
RK05_AU2: R125.1 R126.2 ; also sheet 1
RK05_BF1: C51.1 R93.1 ; also sheet 1
RK05_BF2: C53.1 R50.1 ; also sheet 1
RK05_BH2: R51.1 R52.2 ; also sheet 1
RK05_BK1: R87.1 R88.2 ; also sheet 1
RK05_BP2: R103.1 R104.2 ; also sheet 1
RK05_BT2: R109.1 R110.2 ; also sheet 1
RK05_BU2: R111.1 R112.2 ; also sheet 1
SELECT_0L: R67.1 R68.2 ; also sheet 1
SELECT_1L: R69.1 R70.2 ; also sheet 1
SELECT_2L: R71.1 R72.2 ; also sheet 1
SELECT_3L: R113.1 R114.2 ; also sheet 1
VCC: C47.1 C48.1 C49.1 C50.1 C52.+ R50.2 R51.2 R55.2 R57.2 R63.2 R65.2 R67.2 R69.2 R71.2 R73.2 R75.2 R77.2 R79.2 R81.2 R83.2 R87.2 R89.2 R91.2 R93.2 R99.2 R101.2 R103.2 R105.2 R107.2 R109.2 R111.2 R113.2 R117.2 R119.2 R121.2 R123.2 R125.2 R129.2 R131.2 R133.2 R135.2 R137.2 R139.2 R143.2 R145.2 R147.2 R149.2 ; also sheet 2,3,4

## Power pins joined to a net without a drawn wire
GND: E1.7(P:GND) E2.7(P:GND) E3.8(GND) E4.7(P:GND) E5.7(P:GND) E6.7(P:GND) E7.7(P:GND) E8.8(P:GND) E9.7(P:GND) E10.7(P:GND) E11.7(P:GND) E12.7(P:GND) E13.4(PWR:GND) E14.8(P:GND) E15.7(P:GND) E16.7(P:GND) E17.7(P:GND) E18.7(P:GND) E19.8(GND) E20.8(GND) E21.4(PWR:GND) E22.4(PWR:GND) E23.7(P:GND) E24.7(P:GND) E26.7(P:GND) E27.7(P:GND) E28.7(P:GND) E29.7(P:GND) E30.4(PWR:GND) E31.4(PWR:GND) E32.4(PWR:GND) E33.4(PWR:GND)
VCC: E1.14(P:VCC) E2.14(P:VCC) E3.16(VCC) E4.14(P:VCC) E5.14(P:VCC) E6.14(P:VCC) E7.14(P:VCC) E8.16(P:VCC) E9.14(P:VCC) E10.14(P:VCC) E11.14(P:VCC) E12.14(P:VCC) E13.8(PWR:VCC) E14.16(P:VCC) E15.14(P:VCC) E16.14(P:VCC) E17.14(P:VCC) E18.14(P:VCC) E19.16(VCC) E20.16(VCC) E21.8(PWR:VCC) E22.8(PWR:VCC) E23.14(P:VCC) E24.14(P:VCC) E26.14(P:VCC) E27.14(P:VCC) E28.14(P:VCC) E29.14(P:VCC) E30.8(PWR:VCC) E31.8(PWR:VCC) E32.8(PWR:VCC) E33.8(PWR:VCC)

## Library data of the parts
ADDR_INV POWER SEEK_INC = dec-con:BULB: T 1 3/4 Bulb
BIT0 BIT1-BIT3 CONSTANT_WRITE CYL1 CYL2 CYL4 CYL8 CYL16 CYL32 CYL64 CYL128 DC_ERASE FWD/REV HEAD RTZ RUN WRITE_BUTTON = switch:255SB: SLIDING SWITCH distributor Buerklin, 11G810
C1-C38 C47-C51 C53 C62 C63 = rcl:C-US: CAPACITOR, American symbol
C44 C45 C52 C60 C61 C67 C68 = rcl:CPOL-US: POLARIZED CAPACITOR, American symbol
D1-D4 = diode:1N4148: DIODE
D5 = diode:ZENER-DIODE: Z-Diode
DRIVE FUNCTION = switches5:50-3POLE30: SERIES 50 Single-Deck Rotary Switches three pole 30° Source: www.grayhill.com .. J-15-21.pdf
E1 E16 E23 = 74xx-jameco:74*10: Triple 3-input NAND gate
E2 E5 E11 E18 = 74xx-jameco:74*74: Dual D type positive edge triggered FLIP FLOP, preset and clear
E3 = 74xx-jameco:74*42: 4-line to 10-line DECODER (1-of-10)
E4 E24 = 74xx-jameco:74*20: Dual 4-input NAND gate
E6 E12 = 74xx-jameco:74*04: Hex INVERTER
E7 E10 E15 E17 E26-E29 = 74xx-jameco:74*00: Quad 2-input NAND gate
E8 E14 = 74xx-jameco:74*123: Retriggerable monostable MULTIVIBRATOR
E9 = dec-con:DS8881: Quad 2-input NAND gate, open collector
E13 E21 E22 E30-E33 = 74xx-jameco:DS75451
E19 E20 = 74xx-jameco:74*193: Synchronous 4-bit UP/DOWN COUNTER
E25 = linear:*741: OP AMP
J1 J2 = dec-con:DEC40PINS: 40 pin ribbon connector for BC08, BC11 cables.
Q1 = transistor-small-signal:2N4870: UNIJUNCTION TRANSISTOR
R1-R8 R10-R45 R50-R52 R55-R58 R63-R84 R87-R93 R99-R114 R117-R126 R129-R140 R143-R150 = rcl:R-US_: RESISTOR, American symbol
R9 = pot:TRIM_EU-: POTENTIOMETER
S1 = switches5:320-916: TOGGLE SWITCH distributor RS Components
S2 = switches5:M9040P: TOGGLE SWITCH Marquardt
S3 = switches5:TL32PO: TINY SWITCH ON - MOM Source: http://www2.produktinfo.conrad.com/datenblaetter/700000-724999/705152-da-01-de-Subminiaturschalter_TL_36YO.pdf
S4 = switches5:TL36PO: TINY SWITCH ON - ON Source: http://www2.produktinfo.conrad.com/datenblaetter/700000-724999/705152-da-01-de-Subminiaturschalter_TL_36YO.pdf
SECTOR = switches5:50-1POLE30: SERIES 50 Single-Deck Rotary Switches one pole 30° Source: www.grayhill.com .. J-15-21.pdf

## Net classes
0 default: width 0.508 mm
